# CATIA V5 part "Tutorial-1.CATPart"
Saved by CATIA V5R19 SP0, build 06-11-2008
Part number: c09_tut1
Bounding box of the stored display mesh (mm): x -75 to 138.5, y -40 to 40, z 0 to 100
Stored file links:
  D:\Shriniwas\v5_r19\Part files\c09\c09_tut1.CATPart
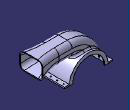
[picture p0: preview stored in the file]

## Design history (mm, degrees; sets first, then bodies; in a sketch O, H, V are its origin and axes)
Body1 (main body)
  Sketch1 on zx-plane, origin (0, 0, 0), H (-1, 0, 0), V (0, 0, 1)
    arc A1 centre (0, 0) radius 60 from (60, 0) to (-60, 0) ccw
    point P1 (-60, 0)
    point P2 (60, 0)
    line L1 (-60, 0) -> (60, 0)
    radius A1 = 60
    coincidence: P1 H, P2 H
    horizontal: L1 H
  Pad1: profile Sketch1, direction (0, 1, 0), length 40, mirrored extent
  Sketch2 on zx-plane, origin (0, 0, 0), H (-1, 0, 0), V (0, 0, 1)
    point P1 (-81.5, 100)
    line L1 (-81.5, 100) -> (-40, 100)
    arc A1 centre (-40, 0) radius 100 from (-40, 100) to (60, 0) cw
    point P4 (60, 0)
    reference projected arc E1 centre (0, 0) radius 60 from (60, 0) to (-60, 0) ccw from edge [face of Pad1 from Sketch1.A1 | end face of Pad1]
    reference projected arc E2 centre (0, 0) radius 60 from (60, 0) to (-60, 0) ccw from edge [face of Pad1 from Sketch1.A1 | end face of Pad1]
    radius A1 = 100
    distance V P1 = 81.5
    distance H L1 = 100
    horizontal: L1 H
    tangency: A1 L1, A1 E2
    coincidence: P4 E1
  Plane1: type Normal, Curve Sketch2, RefPoint Sketch2.P1
  Sketch3 on Plane1, origin (81.5, 0, 0), H (0, 1, 0), V (0, 0, 1)
    line L1 (-28.75, 100) -> (28.75, 100)
    line L2 (28.75, 100) -> (28.75, 58)
    line L3 (28.75, 58) -> (-28.75, 58)
    line L4 (-28.75, 58) -> (-28.75, 100)
    reference projected point E1 (0, 100) from Sketch2.P1
    reference projected point E2 (0, 100) from Sketch2.P1
    length L1 = 57.5
    length L2 = 42
    distance E1 L4 = 28.75
    horizontal: L1 H, L3 H
    vertical: L2 V, L4 V
    coincidence: L1 E2
  Rib1: profile Sketch3, centre curve Sketch2
  Plane2: type Offset, Offset 57, RefPlane face of Rib1, reversed
  Sketch4 on Plane2, origin (138.5, 0, 0), H (0, -1, 0), V (0, 0, 1)
    line L1 (36.25, 100) -> (36.25, 47.5)
    line L2 (36.25, 47.5) -> (-36.25, 47.5)
    line L3 (-36.25, 47.5) -> (-36.25, 100)
    line L4 (-36.25, 100) -> (36.25, 100)
    length L3 = 52.5
    distance V L3 = 36.25
    distance L3 L1 = 72.5
    distance H L4 = 100
    horizontal: L2 H
    vertical: L1 V, L3 V
  Loft1: solid, Sections ({boundary Boundary {extract ExtractElem face of Rib1}}; Sketch4), StartFace face of Rib1
  Fillet1: radius 15, on edge [face of Loft1 | face of Rib1]; edge [face of Rib1 | face of Rib1] (x8); edge [face of Loft1 | face of Loft1] (x2); edge [face of Rib1 | face of Loft1]
  Shell1: ExtOffset 0, IntOffset 2.5, Face (face of Loft1; face of Rib1)
  Fillet2: radius 5, on edge [face of Pad1 from Sketch1.A1 | face of Fillet1]; edge [face of Shell1 | face of Shell1]
  Sketch5 on end face of Pad1, origin (0, 40, 0), H (-1, 0, 0), V (0, 0, 1)
    arc A1 centre (0, 0) radius 50 from (50, 0) to (-50, 0) ccw
    point P1 (-50, 0)
    point P2 (50, 0)
    line L1 (-50, 0) -> (50, 0)
    radius A1 = 50
    coincidence: P1 H, P2 H
    horizontal: L1 H
  Pocket1: profile Sketch5, direction (0, -1, 0), through (limit type 6)
  Sketch6 on start face of Pad1, origin (0, -40, 0), H (1, 0, 0), V (0, 0, 1)
    arc A1 centre (0, 0) radius 15 from (15, 0) to (-15, 0) ccw
    point P1 (15, 0)
    point P2 (-15, 0)
    line L1 (-15, 0) -> (15, 0)
    radius A1 = 15
    coincidence: P1 H, P2 H
    horizontal: L1 H
  Pocket2: profile Sketch6, direction (0, 1, 0), through (limit type 6)
  Sketch7 on end face of Pad1, origin (0, 40, 0), H (-1, 0, 0), V (0, 0, 1)
    line L1 (59.8665, 4) -> (75, 4)
    line L2 (60, 0) -> (75, 0)
    line L3 (75, 4) -> (75, 0)
    projected arc E1 centre (0, 0) radius 60 from (60, 0) to (-60, 0) ccw from edge [face of Pad1 from Sketch1.A1 | end face of Pad1]
    projected arc E2 centre (0, 0) radius 60 from (60, 0) to (59.8665, 4) ccw from edge [face of Pad1 from Sketch1.A1 | end face of Pad1]
    point P5 (59.8665, 4)
    length L3 = 4
    distance V L3 = 75
    horizontal: L1 H, L2 H
    vertical: L3 V
    coincidence: E1 P5
  Pad2: profile Sketch7, direction (0, -1, 0), up to start face of Pad1
  Mirror1: of Pad2, about yz-plane
  Sketch8 on face of Pad2 from Sketch7.L1, origin (-64.0831, -0.1557, 4), H (1, 0, 0), V (0, 1, 0)
    point P1 (-3.4169, -29.8443)
    reference projected line E1 (-10.9169, 40.1557) -> (-10.9169, -39.8443) from edge [face of Pad2 from Sketch7.L3 | face of Pad2 from Sketch7.L1]
    reference projected line E2 (4.2165, -39.8443) -> (-10.9169, -39.8443) from edge [face of Pad2 from Sketch7.L1 | face of Pad1]
    distance P1 E1 = 7.5
    distance E2 P1 = 10
  Hole1: placed by Sketch8, at (-67.5, -30, 4) direction (0, 0, -1), diameter 4, depth 10
  RectPattern1: of Hole1, direction 1 instances 4, spacing 20, along edge [face of Pad2 from Sketch7.L3 | face of Pad2 from Sketch7.L1] reversed, direction 2 instances 2, spacing 135, along edge [face of Rib1 | face of Pad1] reversed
